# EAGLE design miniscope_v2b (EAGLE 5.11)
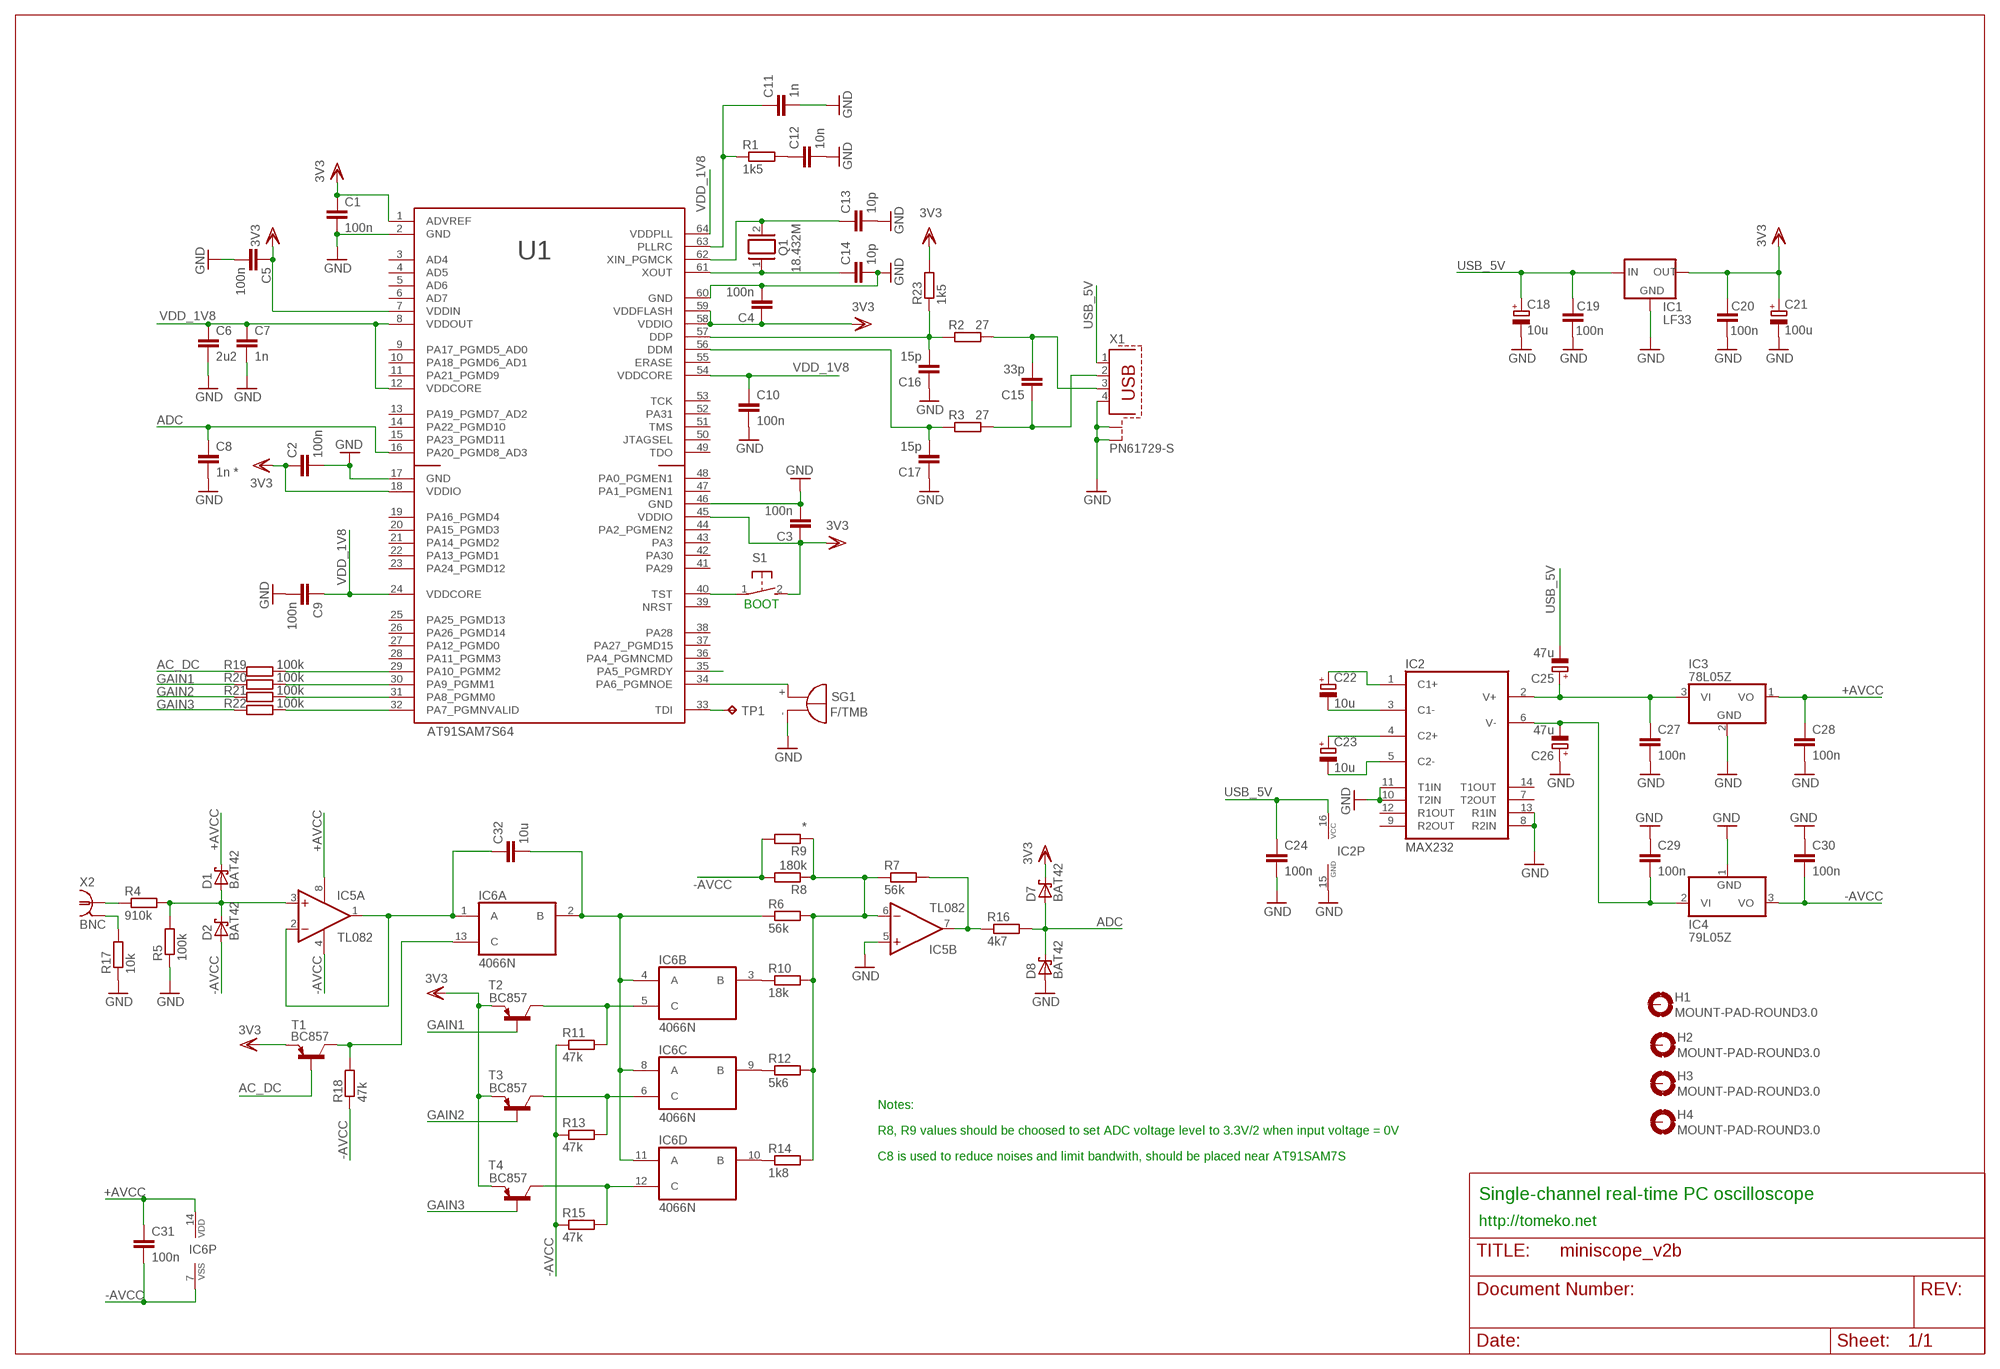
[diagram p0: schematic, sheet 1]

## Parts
C1  100n  C-EUC0805K  [C0805K]
C2  100n  C-EUC0805K  [C0805K]
C3  100n  C-EUC0805K  [C0805K]
C4  100n  C-EUC0805K  [C0805K]
C5  100n  C-EUC0805K  [C0805K]
C6  2u2  C-EUC1206K  [C1206K]
C7  1n  C-EUC0805K  [C0805K]
C8  1n *  C-EUC0805K  [C0805K]
C9  100n  C-EUC0805K  [C0805K]
C10  100n  C-EUC0805K  [C0805K]
C11  1n  C-EUC0805K  [C0805K]
C12  10n  C-EUC0805K  [C0805K]
C13  10p  C-EUC0805K  [C0805K]
C14  10p  C-EUC0805K  [C0805K]
C15  33p  C-EUC0805K  [C0805K]
C16  15p  C-EUC0805K  [C0805K]
C17  15p  C-EUC0805K  [C0805K]
C18  10u  CPOL-EUE2.5-5  [E2,5-5]
C19  100n  C-EUC0805K  [C0805K]
C20  100n  C-EUC0805K  [C0805K]
C21  100u  CPOL-EUE2.5-6  [E2,5-6]
C22  10u  CPOL-EUE2.5-5  [E2,5-5]
C23  10u  CPOL-EUE2.5-5  [E2,5-5]
C24  100n  C-EUC0805K  [C0805K]
C25  47u  CPOL-EUE2.5-6  [E2,5-6]
C26  47u  CPOL-EUE2.5-6  [E2,5-6]
C27  100n  C-EUC0805K  [C0805K]
C28  100n  C-EUC0805K  [C0805K]
C29  100n  C-EUC0805K  [C0805K]
C30  100n  C-EUC0805K  [C0805K]
C31  100n  C-EUC0805K  [C0805K]
C32  10u  C-EUC1206K  [C1206K]
D1  BAT42  [DO35-10]
D2  BAT42  [DO35-10]
D7  BAT42  [DO35-10]
D8  BAT42  [DO35-10]
H1  MOUNT-PAD-ROUND3.0  [3,0-PAD]
H2  MOUNT-PAD-ROUND3.0  [3,0-PAD]
H3  MOUNT-PAD-ROUND3.0  [3,0-PAD]
H4  MOUNT-PAD-ROUND3.0  [3,0-PAD]
IC1  LF33  LFXXCV  [DPACK_1]
IC2  MAX232  [DIL16]
IC3  78L05Z  [TO92]
IC4  79L05Z  [TO92]
IC5  TL082  NE5532N  [DIL08]
IC6  4066N  [DIL14]
Q1  18.432M  XTAL/S  [QS]
R1  1k5  R-R0805  [R0805]
R2  27  R-R0805  [R0805]
R3  27  R-R0805  [R0805]
R4  910k  R-R0805  [R0805]
R5  100k  R-R0805  [R0805]
R6  56k  R-R0805  [R0805]
R7  56k  R-R0805  [R0805]
R8  180k  R-R0805  [R0805]
R9  *  R-R0805  [R0805]
R10  18k  R-R0805  [R0805]
R11  47k  R-R0805  [R0805]
R12  5k6  R-R0805  [R0805]
R13  47k  R-R0805  [R0805]
R14  1k8  R-R0805  [R0805]
R15  47k  R-R0805  [R0805]
R16  4k7  R-R0805  [R0805]
R17  10k  R-R0805  [R0805]
R18  47k  R-R0805  [R0805]
R19  100k  R-R0805  [R0805]
R20  100k  R-R0805  [R0805]
R21  100k  R-R0805  [R0805]
R22  100k  R-R0805  [R0805]
R23  1k5  R-R0805  [R0805]
S1  31-XX  [B3F-31XX]
SG1  F/TMB  [F/TMB]
T1  BC857  BC857B-PNP-SOT23-BEC  [SOT23-BEC]
T2  BC857  BC857B-PNP-SOT23-BEC  [SOT23-BEC]
T3  BC857  BC857B-PNP-SOT23-BEC  [SOT23-BEC]
T4  BC857  BC857B-PNP-SOT23-BEC  [SOT23-BEC]
TP1  TPPAD1-13  [P1-13]
U1  AT91SAM7S64  AT91SAM7S64_LQFP64  [LQFP64]
X1  PN61729-S  [PN61729-S]
X2  BNC  1-227161-0  [AMP_227161]

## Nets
+AVCC: C28.1 C31.1 D1.C IC3.1(VO) IC5.8(P:V+) IC6.14(P:VDD)
-AVCC: C30.2 C31.2 D2.A IC4.3(VO) IC5.4(P:V-) IC6.7(P:VSS) R8.2 R9.2 R11.1 R13.1 R15.1 R18.1
AC_DC: R19.1 T1.B
ADC: C8.1 D7.A D8.C R16.2 U1.16(PA20_PGMD8_AD3)
GAIN1: R20.1 T2.B
GAIN2: R21.1 T3.B
GAIN3: R22.1 T4.B
GND: C1.2 C2.2 C3.2 C4.2 C5.2 C6.2 C7.2 C8.2 C9.2 C10.2 C11.2 C12.2 C13.2 C14.2 C16.1 C17.1 C18.- C19.1 C20.1 C21.- C24.2 C26.+ C27.2 C28.2 C29.1 C30.1 D8.A IC1.C(GND) IC2.8(R2IN) IC2.10(T2IN) IC2.11(T1IN) IC2.13(R1IN) IC2.15(GND) IC3.2(GND) IC4.1(GND) IC5.5(B:+IN) R5.1 R17.1 SG1.- U1.2(GND) U1.17(GND) U1.46(GND) U1.60(GND) X1.4 X1.S1 X1.S2
N$1: S1.1(P) U1.40(TST)
N$2: C11.1 R1.1 U1.63(PLLRC)
N$3: C12.1 R1.2
N$4: C14.1 Q1.1 U1.61(XOUT)
N$5: C13.1 Q1.2 U1.62(XIN_PGMCK)
N$6: C16.2 R2.1 R23.1 U1.57(DDP)
N$7: C17.2 R3.1 U1.56(DDM)
N$8: C15.2 R2.2 X1.3
N$9: C15.1 R3.2 X1.2
N$10: C25.+ C27.1 IC2.2(V+) IC3.3(VI)
N$11: C22.- IC2.3(C1-)
N$12: C22.+ IC2.1(C1+)
N$13: C23.+ IC2.4(C2+)
N$14: C23.- IC2.5(C2-)
N$15: R4.1 X2.1
N$16: C26.- C29.2 IC2.6(V-) IC4.2(VI)
N$17: D1.A D2.C IC5.3(A:+IN) R4.2 R5.2
N$18: C32.1 IC5.1(A:OUT) IC5.2(A:-IN) IC6.1(A:A)
N$19: R17.2 X2.2(GND)
N$20: C32.2 IC6.2(A:B) IC6.4(B:A) IC6.8(C:A) IC6.11(D:A) R6.1
N$21: IC5.6(B:-IN) R6.2 R7.1 R8.1 R9.1 R10.2 R12.2 R14.2
N$22: IC5.7(B:OUT) R7.2 R16.1
N$23: IC6.9(C:B) R12.1
N$24: IC6.6(C:C) R13.2 T3.C
N$25: IC6.3(B:B) R10.1
N$26: IC6.10(D:B) R14.1
N$27: IC6.5(B:C) R11.2 T2.C
N$28: R19.2 U1.29(PA10_PGMM2)
N$29: IC6.12(D:C) R15.2 T4.C
N$30: R20.2 U1.30(PA9_PGMM1)
N$31: IC6.13(A:C) R18.2 T1.C
N$32: R21.2 U1.31(PA8_PGMM0)
N$33: R22.2 U1.32(PA7_PGMNVALID)
N$34: SG1.+ U1.34(PA6_PGMNOE)
N$35: U1.35(PA5_PGMRDY)
N$36: TP1.TP U1.33(TDI)
USB_5V: C18.+ C19.2 C24.1 C25.- IC1.B(IN) IC2.16(VCC) X1.1
VDD: C1.1 C2.1 C3.1 C4.1 C5.1 C20.2 C21.+ D7.C IC1.E(OUT) R23.2 S1.2(S) T1.E T2.E T3.E T4.E U1.1(ADVREF) U1.7(VDDIN) U1.18(VDDIO) U1.45(VDDIO) U1.58(VDDIO) U1.59(VDDFLASH) ; supply symbol labelled 3V3
VDD_1V8: C6.1 C7.1 C9.1 C10.1 U1.8(VDDOUT) U1.12(VDDCORE) U1.24(VDDCORE) U1.54(VDDCORE) U1.64(VDDPLL)
Unconnected: H1.B3,0(MOUNT) H2.B3,0(MOUNT) H3.B3,0(MOUNT) H4.B3,0(MOUNT) IC2.7(T2OUT) IC2.9(R2OUT) IC2.12(R1OUT) IC2.14(T1OUT) U1.3(AD4) U1.4(AD5) U1.5(AD6) U1.6(AD7) U1.9(PA17_PGMD5_AD0) U1.10(PA18_PGMD6_AD1) U1.11(PA21_PGMD9) U1.13(PA19_PGMD7_AD2) U1.14(PA22_PGMD10) U1.15(PA23_PGMD11) U1.19(PA16_PGMD4) U1.20(PA15_PGMD3) U1.23(PA24_PGMD12) U1.25(PA25_PGMD13) U1.26(PA26_PGMD14) U1.27(PA12_PGMD0) U1.28(PA11_PGMM3) U1.36(PA4_PGMNCMD) U1.37(PA27_PGMD15) U1.38(PA28) U1.39(NRST) U1.41(PA29) U1.42(PA30) U1.43(PA3) U1.44(PA2_PGMEN2) U1.47(PA1_PGMEN1) U1.48(PA0_PGMEN1) U1.49(TDO) U1.50(JTAGSEL) U1.51(TMS) U1.55(ERASE)

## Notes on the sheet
- BOOT
- Notes:
- R8, R9 values should be choosed to set ADC voltage level to 3.3V/2 when input voltage = 0V
- C8 is used to reduce noises and limit bandwith, should be placed near AT91SAM7S
- Single-channel real-time PC oscilloscope
- http://tomeko.net

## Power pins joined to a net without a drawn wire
PA13_PGMD1: U1.22(PA13_PGMD1)
PA14_PGMD2: U1.21(PA14_PGMD2)
PA31: U1.52(PA31)
TCK: U1.53(TCK)

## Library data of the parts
C1-C17 C19 C20 C24 C27-C32 = resistor:C-EU: CAPACITOR, European symbol
C18 C21-C23 C25 C26 = resistor:CPOL-EU: POLARIZED CAPACITOR, European symbol
D1 D2 D7 D8 = diode:BAT42: DIODE
H1-H4 = holes:MOUNT-PAD-ROUND: MOUNTING PAD, round
IC1 = lf33:LFXXCV: VOLTAGE REGULATOR
IC2 = maxim:MAX232: RS232 TRANSEIVER; MF: MAXIM; MPN: MAX232ACPE+; OC_FARNELL: 9723773; OC_NEWARK: 68K4544
IC3 = linear:78*: Positive VOLTAGE REGULATOR Source: http://cache.national.com/ds/LM/LM78L05.pdf http://www.fairchildsemi.com/ds/LM/LM7805.pdf
IC4 = linear:79*: Negative VOLTAGE REGULATOR
IC5 = linear:NE5532: AUDIO AMPLIFIER
IC6 = 40xx:4066: Quad bilateral ANALOG SWITCH
Q1 = special:XTAL/S: CRYSTAL
R1-R23 = quantum-sensor:R: Resistor
S1 = switch-omron:31-XX: OMRON SWITCH; MPN: B3F-3100; OC_FARNELL: 959704; OC_NEWARK: 36M3582
SG1 = buzzer:F/TMB: BUZZER; OC_FARNELL: unknown; OC_NEWARK: unknown
T1-T4 = transistor:*-PNP-: PNP Transistror
TP1 = testpad:TP: Test pad
U1 = atmel_prototype_header:AT91SAM7S64: Atmel AT91 ARM Thumb-based Microcontroller. LQFP64 package.
X1 = con-berg:PN61729-S: BERG USB connector; OC_FARNELL: unknown; OC_NEWARK: unknown
X2 = con-coax:?227161*: JACK, RIGHT ANGLE, 50 OHM, PCB, BNC; MF: TYCO ELECTRONICS; MPN: 1-227161; OC_FARNELL: unknown; OC_NEWARK: 33B3200

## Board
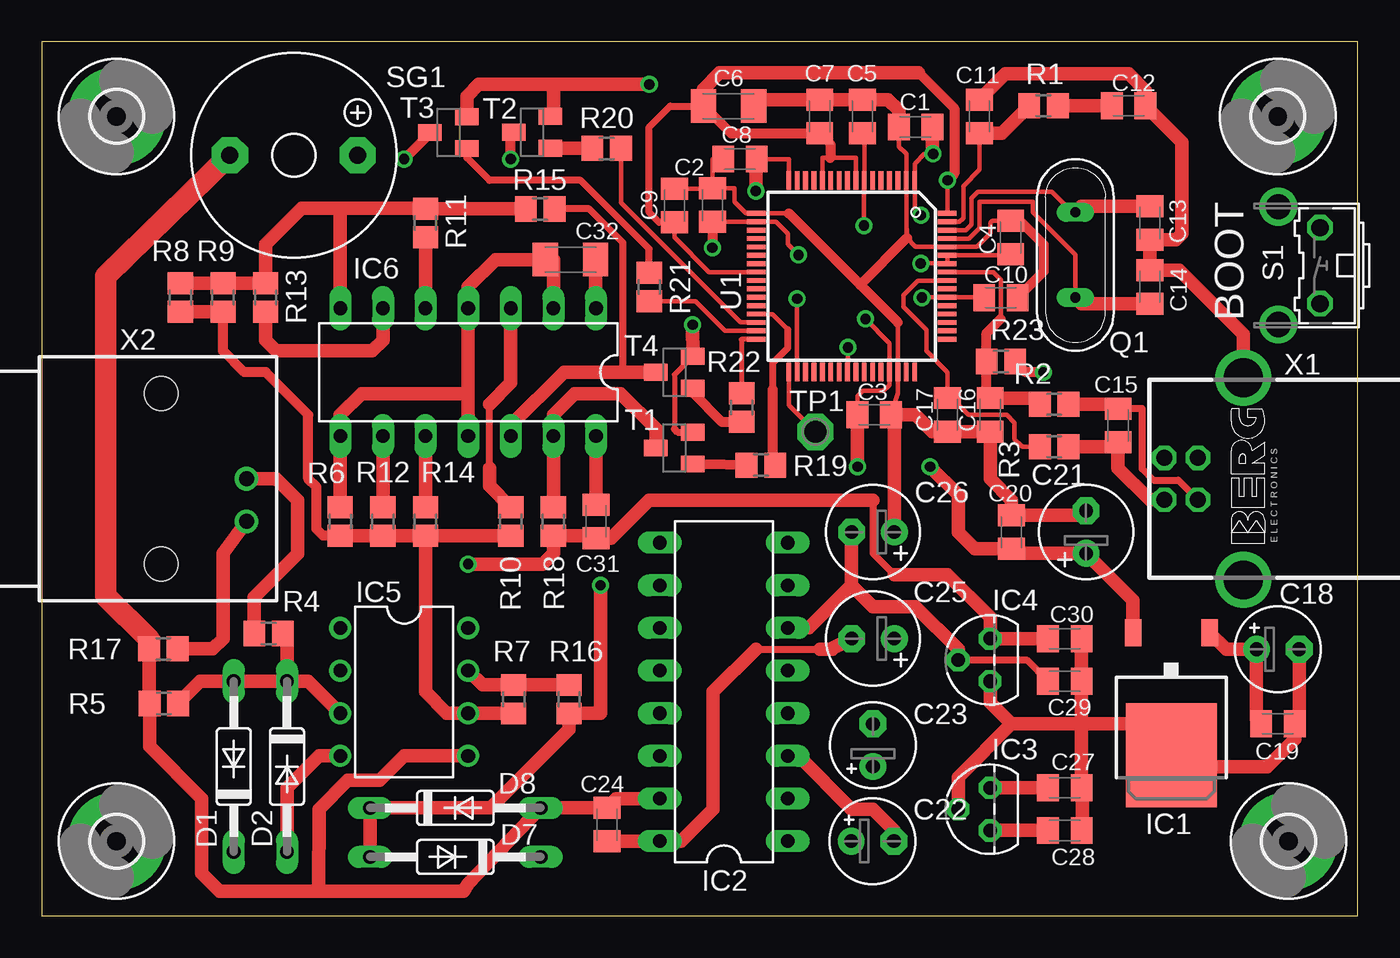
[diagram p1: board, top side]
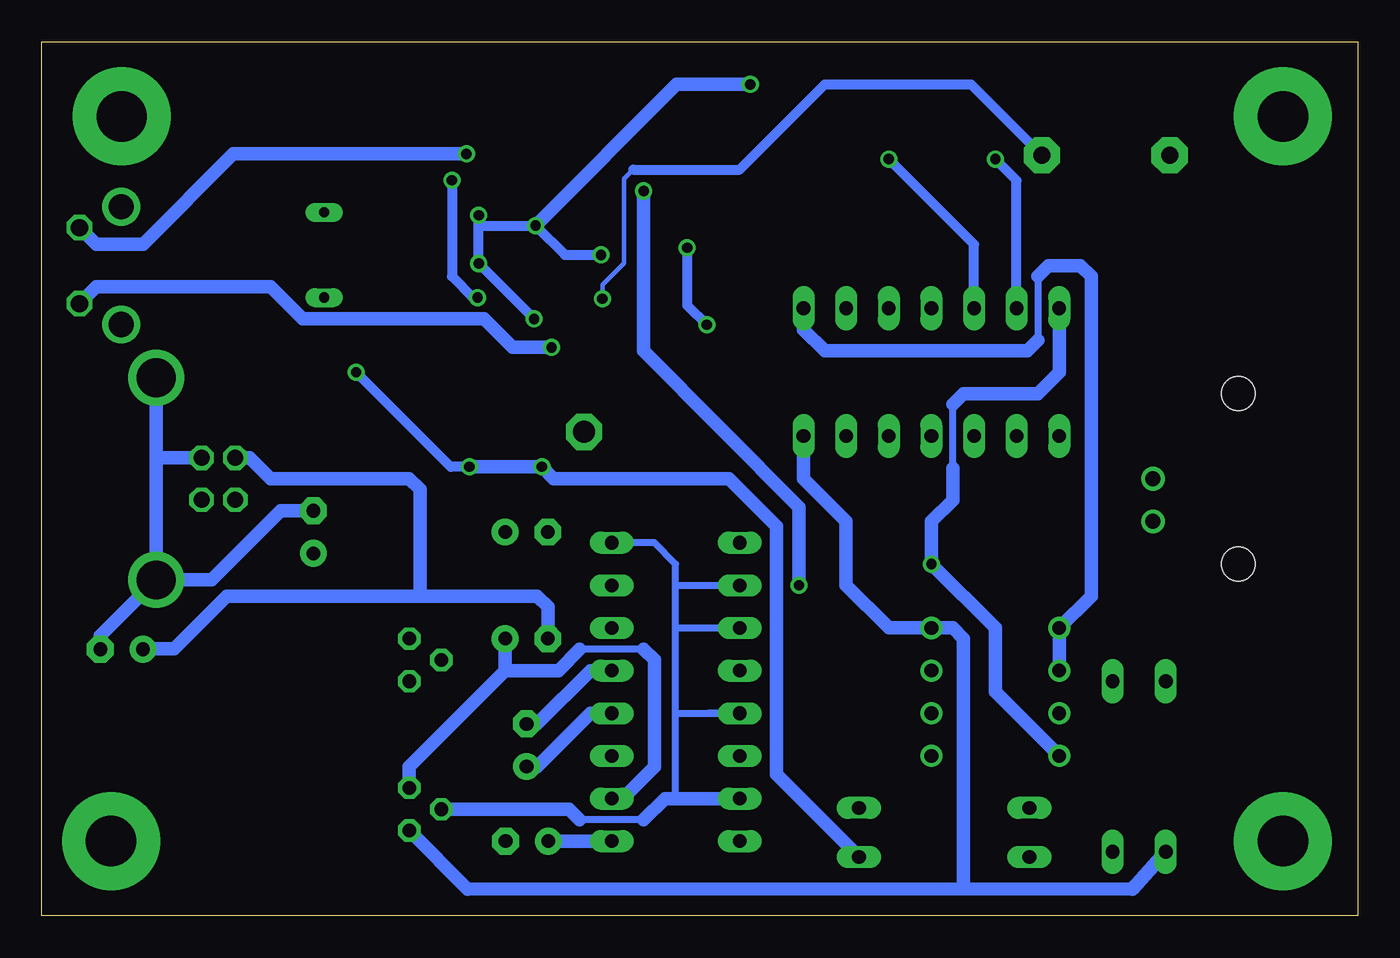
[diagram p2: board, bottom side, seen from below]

Size 78.41 x 52.06 mm. Coordinates in mm from the lower left corner, seen from the top.
Outline: 0,0 78.41,0 78.41,52.06 0,52.06 0,0
Copper layers (1*16): Top 0.035mm / dielectric 1.5mm / Bottom 0.035mm
Design rules "default *": minimum track width 10mil, minimum drill 24mil, track to track 8mil, track to pad 8mil, pad to pad 8mil, via to via 8mil, smd to smd 8mil, copper to edge 40mil, drill to drill 8mil, minimum pad ring 10mil, minimum via ring 8mil, stop-mask expansion 4mil, vias tented up to drill 0mil, thermal gap 10mil

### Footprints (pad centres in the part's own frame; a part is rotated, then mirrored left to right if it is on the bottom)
C0805K = smd 1.3 x 1.6: 1 -1,0; 2 1,0
C1206K = smd 1.5 x 2: 1 -1.5,0; 2 1.5,0
E2,5-5 = drill 0.813 pad 1.6 round: + -1.27,0 | drill 0.813 pad 1.6 octagon: - 1.27,0
E2,5-6 = drill 0.813 pad 1.6 round: + -1.27,0 | drill 0.813 pad 1.6 octagon: - 1.27,0
DO35-10 = drill 0.813 long: A 5.08,0; C -5.08,0
3,0-PAD = drill 3 pad 5.842 round: B3,0 0,0
DPACK_1 = smd 1 x 1.6: B -2.28,-4.8; E 2.28,-4.8 | smd 5.4 x 6.2: C 0,2.5
DIL16 = drill 0.813 long: 1 -8.89,-3.81; 2 -6.35,-3.81; 3 -3.81,-3.81; 4 -1.27,-3.81; 5 1.27,-3.81; 6 3.81,-3.81; 7 6.35,-3.81; 8 8.89,-3.81; 9 8.89,3.81; 10 6.35,3.81; 11 3.81,3.81; 12 1.27,3.81; 13 -1.27,3.81; 14 -3.81,3.81; 15 -6.35,3.81; 16 -8.89,3.81
TO92 = drill 0.813 octagon: 1 -1.27,0; 2 0,1.905; 3 1.27,0
DIL08 = drill 0.813 pad 1.27 round: 1 -3.81,-3.81; 2 -1.27,-3.81; 3 1.27,-3.81; 4 3.81,-3.81; 5 3.81,3.81; 6 1.27,3.81; 7 -1.27,3.81; 8 -3.81,3.81
DIL14 = drill 0.813 long: 1 -7.62,-3.81; 2 -5.08,-3.81; 3 -2.54,-3.81; 4 0,-3.81; 5 2.54,-3.81; 6 5.08,-3.81; 7 7.62,-3.81; 8 7.62,3.81; 9 5.08,3.81; 10 2.54,3.81; 11 0,3.81; 12 -2.54,3.81; 13 -5.08,3.81; 14 -7.62,3.81
QS = drill 0.61 long: 1 -2.54,0; 2 2.54,0
R0805 = smd 1.3 x 1.5: 1 -0.85,0; 2 0.85,0
B3F-31XX = drill 1.016 octagon: 1 -2.261,-1.245; 2 2.261,-1.245 | drill 1.499 pad 2.159 round: 3 -3.505,1.245; 4 3.505,1.245
F/TMB = drill 1.016 pad 2.159 octagon: + 3.81,0; - -3.81,0
SOT23-BEC = smd 1 x 1.4: B -0.95,-1.1; C 0,1.1; E 0.95,-1.1
P1-13 = drill 1.321 pad 2.159 octagon: TP 0,0
LQFP64 = smd 1.1 x 0.285: 1 -5.7,3.75; 2 -5.7,3.25; 3 -5.7,2.75; 4 -5.7,2.25; 5 -5.7,1.75; 6 -5.7,1.25; 7 -5.7,0.75; 8 -5.7,0.25; 9 -5.7,-0.25; 10 -5.7,-0.75; 11 -5.7,-1.25; 12 -5.7,-1.75; 13 -5.7,-2.25; 14 -5.7,-2.75; 15 -5.7,-3.25; 16 -5.7,-3.75; 33 5.7,-3.75; 34 5.7,-3.25; 35 5.7,-2.75; 36 5.7,-2.25; 37 5.7,-1.75; 38 5.7,-1.25; 39 5.7,-0.75; 40 5.7,-0.25; 41 5.7,0.25; 42 5.7,0.75; 43 5.7,1.25; 44 5.7,1.75; 45 5.7,2.25; 46 5.7,2.75; 47 5.7,3.25; 48 5.7,3.75 | smd 0.285 x 1.1: 17 -3.75,-5.7; 18 -3.25,-5.7; 19 -2.75,-5.7; 20 -2.25,-5.7; 21 -1.75,-5.7; 22 -1.25,-5.7; 23 -0.75,-5.7; 24 -0.25,-5.7; 25 0.25,-5.7; 26 0.75,-5.7; 27 1.25,-5.7; 28 1.75,-5.7; 29 2.25,-5.7; 30 2.75,-5.7; 31 3.25,-5.7; 32 3.75,-5.7; 49 3.75,5.7; 50 3.25,5.7; 51 2.75,5.7; 52 2.25,5.7; 53 1.75,5.7; 54 1.25,5.7; 55 0.75,5.7; 56 0.25,5.7; 57 -0.25,5.7; 58 -0.75,5.7; 59 -1.25,5.7; 60 -1.75,5.7; 61 -2.25,5.7; 62 -2.75,5.7; 63 -3.25,5.7; 64 -3.75,5.7
PN61729-S = drill 0.95 octagon: 1 1.25,4.71; 2 -1.25,4.71; 3 -1.25,2.71; 4 1.25,2.71 | drill 2.3 pad 2.9 round: S1 -6.02,0; S2 6.02,0
AMP_227161 = drill 0.9 pad 1.27 round: 1 0,-5.08; 2 -2.54,-5.08 | hole 2: -5.08,0; 5.08,0

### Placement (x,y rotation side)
C1  52.07,46.99 180 top
C2  39.95,42.34 90 top
C3  49.61,29.84 0 top
C4  57.73,40.41 90 top
C5  48.9,47.62 90 top
C6  40.92,48.23 0 top
C7  46.35,47.62 90 top
C8  41.61,45.09 180 top
C9  37.69,42.32 90 top
C10  57.15,36.83 0 top
C11  55.88,47.62 90 top
C12  64.77,48.26 0 top
C13  66.04,41.27 270 top
C14  66.04,37.47 90 top
C15  64.14,29.21 90 top
C16  56.52,29.84 90 top
C17  53.98,29.84 90 top
C18  73.66,15.88 0 top
C19  73.66,11.43 180 top
C20  57.78,22.86 270 top
C21  62.23,22.86 90 top
C22  49.5,4.45 0 top
C23  49.53,10.16 90 top
C24  33.68,5.44 90 top
C25  49.53,16.51 180 top
C26  49.53,22.86 180 top
C27  60.96,7.62 0 top
C28  60.96,5.08 0 top
C29  60.96,13.97 180 top
C30  60.96,16.51 180 top
C31  33.02,23.5 270 top
C32  31.5,39.09 180 top
D1  11.43,8.89 90 top
D2  14.61,8.89 270 top
D7  24.64,3.51 180 top
D8  24.64,6.43 0 top
H1  74.3,4.45 0 top
H2  73.66,47.62 0 top
H3  4.45,47.62 0 top
H4  4.45,4.45 0 top
IC1  67.31,12.06 180 top
IC2  40.64,13.34 90 top
IC3  56.52,6.35 90 top
IC4  56.52,15.24 90 top
IC5  21.59,13.34 270 top
IC6  25.4,32.38 180 top
Q1  61.59,39.37 90 top
R1  59.69,48.26 0 top
R2  60.33,30.48 0 top
R3  60.33,27.94 0 top
R4  13.51,16.81 0 top
R5  7.26,12.65 0 top
R6  17.78,23.5 270 top
R7  28.12,12.9 90 top
R8  8.26,36.83 90 top
R9  10.79,36.83 90 top
R10  27.94,23.5 270 top
R11  22.86,41.27 270 top
R12  20.32,23.5 270 top
R13  13.34,36.83 270 top
R14  22.86,23.5 270 top
R15  29.69,42.11 0 top
R16  31.42,12.9 270 top
R17  7.24,15.9 0 top
R18  30.48,23.5 90 top
R19  42.85,26.85 0 top
R20  33.66,45.72 0 top
R21  36.2,37.47 270 top
R22  41.71,30.28 90 top
R23  57.15,33.02 0 top
S1  74.93,38.73 90 top
SG1  15.01,45.31 0 top
T1  37.69,27.86 90 top
T2  29.21,46.69 90 top
T3  24.23,46.66 90 top
T4  37.69,32.38 90 top
TP1  46.1,28.83 0 top
U1  48.26,38.1 270 top
X1  71.6,26.04 90 top
X2  7.11,26.04 90 top

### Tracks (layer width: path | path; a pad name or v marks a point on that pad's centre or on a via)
+AVCC
  Top 0.813: IC3.1 C28.1 | IC6.14 C31.1
  Bottom 0.813: D1.C 13.44,1.57 23.29,1.6 23.5,1.6 | 23.5,1.6 53.03,1.57 IC3.1 | IC6.14 33.02,26.04 30.48,23.5 30.48,19.68 27.94,17.14 IC5.8 24.13,17.14 23.5,16.51 23.5,1.6 | 23.5,1.6
-AVCC  (via drill 0.61)
  Top 0.254: R11.1 22.81,42.14
  Top 0.406: 49.53,24.77 49.53,21.59 50.8,20.32
  Top 0.813: R8.2 R9.2 R13.1 13.34,40.01 15.47,42.14 17.78,42.14 | C30.2 IC4.3 56.52,17.78 53.98,20.32 50.8,20.32 | 49.53,24.77 36.2,24.77 33.92,22.5 C31.2 32.87,22.64 R18.1 30.48,21.59 29.84,20.95 v25.4,20.95 | D2.A 14.61,7.62 16.51,9.53 IC5.4 | R15.1 27.51,42.12 R11.1 22.85,42.14 17.78,42.14 | IC6.7 17.78,42.14
  Bottom 0.406: 24.13,26.67 24.13,30.48
  Bottom 0.813: IC5.4 21.59,13.34 21.59,17.14 v25.4,20.95 25.4,23.5 24.13,24.77 24.13,26.67 | 24.13,30.48 23.5,31.11 19.05,31.11 17.78,32.38 IC6.7
AC_DC
  Top 0.61: R19.1 39.44,26.9 T1.B
ADC  (via drill 0.61)
  Top 0.254: U1.16 44.51,45.09 C8.1
  Top 0.813: D7.A D8.C 26.75,6.43 31.42,11.1 R16.2 33.3,12.05 v33.3,19.68 | v42.55,43.18 42.55,45.02 C8.1
  Bottom 0.813: v33.3,19.68 33.3,24.33 42.55,33.66 v42.55,43.18
GAIN1
  Top 0.813: T2.B 32.79,45.73 R20.1
GAIN2
  Top 0.406: R21.1 36.2,39.73 32.11,43.81 26.67,43.81 25.33,45.15 T3.B
GAIN3
  Top 0.61: R22.1 41.69,29.41 40.54,29.41 38.79,31.16 T4.B
GND
  Top 0.254: 51.51,41.53 U1.2 51.51,45.39 51.08,45.82 C1.2 | 51.56,40.39 51.51,41.53 | 44.51,41.85 U1.17 41.97,41.85 41.27,42.55 41.27,43.34 C2.2 | 51.01,35.35 U1.46 51,31.14 C3.2 | 51.51,41.53 51.51,40.44 51.56,40.39 | 51.56,40.39 52.07,39.85 53.93,39.85 U1.60 55.73,39.85 56.52,40.66 56.52,41.27 56.65,41.41 C4.2 | 62,5.08 C28.2 | C27.2 62,7.62 | R5.1 6.4,12.7 | 6.4,15.85 R17.1 | 74.37,9.96 74.68,10.26 74.68,11.38 C19.1 | 67.36,9.96 67.36,9.65 IC1.C | C2.2 39.95,45.09 C8.2 | C2.2 39.95,43.32 C9.2
  Top 0.406: C7.2 45.97,48.23
  Top 0.61: 48.77,37.59 51.56,40.39 | 48.77,37.59 44.51,41.85 | 51.01,35.35 48.77,37.59 | C10.2 59.69,38.37 59.69,40.01 58.28,41.41 C4.2
  Top 0.813: 6.4,15.85 6.4,12.66 R5.1 6.41,10.1 9.53,6.99 9.53,2.54 10.59,1.45 16.48,1.45 | IC2.15 34.23,6.99 C24.2 D8.A 25.4,1.91 25.12,1.47 16.48,1.45 | IC5.5 21.59,9.53 20.12,8.08 18.21,8.08 16.51,6.35 16.48,1.45 | 62,5.08 62,7.58 C27.2 61.96,11.43 | C30.1 C29.1 61.96,11.43 | IC4.1 56.52,12.7 57.78,11.43 | 57.78,11.43 61.96,11.43 | 61.96,11.43 65.44,11.43 IC1.C | IC3.2 54.61,8.26 57.78,11.43 | C18.- 74.93,11.7 C19.1 74.66,10.53 73.03,8.89 68.43,8.89 67.36,9.96 | C21.- 61.96,23.86 C20.1 57.78,24.77 56.52,26.04 C16.1 C17.1 53.07,28.84 52.07,29.84 C3.2 50.8,29.65 C26.+ | X1.S2 71.6,34.65 67.78,38.47 C14.2 C13.2 67.58,40.27 67.94,40.64 67.94,46.09 C12.2 65.77,49.16 64.77,50.16 57.42,50.16 C11.2 | C1.2 51.07,47.99 50.44,48.62 C5.2 C7.2 42.81,48.62 C6.2
  Top 1.27: SG1.- 3.81,38.1 3.81,19.05 6.39,16.47 R17.1
  Bottom 0.406: 42.55,5.71 46.35,5.71 | IC2.8 41.91,22.23 40.64,20.95 40.64,19.68 | 38.73,12.06 IC2.13 40.64,12.06 | 40.64,6.99 40.64,12.06 | 40.64,12.06 40.64,17.14 | 40.64,17.14 40.64,19.68 | 40.64,19.68 IC2.10 | 40.64,17.14 IC2.11
  Bottom 0.813: X1.S1 74.93,16.69 C18.- | IC2.15 40.64,6.99 41.27,6.99 42.55,5.71 | 46.35,5.71 46.99,6.35 IC3.2 | C21.- 64.19,24.13 68.3,20.02 X1.S1 | X1.S1 71.6,27.3 | 71.6,27.3 X1.S2 | X1.4 71.58,27.29 71.6,27.3
N$1  (via drill 0.61)
  Top 0.254: U1.40 48.03,32.42 v48.03,33.86
  Bottom 0.254: v48.03,33.86 48.11,33.93
  Bottom 0.813: S1.1 75.18,37.47 64.77,37.47 62.87,35.56 52.07,35.56 50.37,33.86 v48.03,33.86
N$2
  Top 0.254: U1.63 54.69,41.35 54.91,41.55 54.91,43.46 55.88,44.45 C11.1
  Top 0.813: C11.1 57.2,46.62 R1.1
N$3
  Top 0.813: R1.2 C12.1
N$4
  Top 0.254: Q1.1 61.59,39.37 59.05,41.91 59.05,42.55 55.88,42.55 55.88,41.02 55.91,41 55.26,40.35 U1.61
  Top 0.813: C14.1 61.96,36.47 Q1.1
N$5
  Top 0.254: U1.62 55.07,40.84 55.4,41.17 55.4,42.75 55.78,43.13 60.2,43.13 61.42,41.91 Q1.2
  Top 0.813: C13.1 61.96,42.27 Q1.2
N$6
  Top 0.254: U1.57 56.69,38.35 57.15,37.9 57.15,35.56
  Top 0.61: C16.2 56.3,31.06 R23.1 56.3,34.71 57.15,35.56
  Top 0.813: C16.2 59.11,30.84 R2.1
N$7
  Top 0.254: U1.56 52.22,37.85 51.36,36.98 51.36,36.27 52.7,34.92 52.7,33.66 53.98,32.38 C17.2 54.22,30.84 55.22,29.84 57.51,29.84 57.96,29.39 57.96,28.4 58.42,27.94 R3.1
N$8
  Top 0.406: X1.3 67.72,25.96 66.24,25.96 65.58,26.62 65.58,30.21 C15.2
  Top 0.813: R2.2 63.87,30.48 C15.2
N$9
  Top 0.813: X1.2 66.02,24.79 64.14,26.67 C15.1 63.87,27.94 R3.2
N$10
  Top 0.813: IC3.3 C27.1
  Bottom 0.406: 42.55,15.88 46.35,15.88
  Bottom 0.813: IC3.3 56.52,8.89 50.8,14.61 | 50.8,14.61 C25.+ | IC2.2 43.81,6.99 41.91,8.89 41.91,15.24 42.55,15.88 | 46.35,15.88 47.62,14.61 50.8,14.61
N$11
  Top 0.813: C22.- 50.77,5.11 49.53,6.35 48.26,6.35 45.09,9.53 IC2.3
N$12
  Bottom 0.813: IC2.1 C22.+
N$13
  Bottom 0.813: C23.+ 48.9,8.89 45.72,12.06 IC2.4
N$14
  Bottom 0.813: C23.- 48.9,11.43 45.72,14.61 IC2.5
N$15
  Top 0.813: X2.1 13.97,26.04 15.24,24.77 15.24,21.57 12.65,18.97 12.65,16.83 R4.1
N$16
  Top 0.406: IC4.2 58.69,15.24 C29.2
  Top 0.813: IC2.6 45.72,17.14 48.26,19.68 | 48.26,19.68 C26.- | IC4.2 54.61,15.88 52.07,18.41 49.53,18.41 48.26,19.68
N$17
  Top 0.813: R5.2 9.44,13.97 D1.A D2.C | R4.2 arc-90 14.61,16.57 D2.C | IC5.3 15.88,13.97 D2.C
N$18
  Top 0.813: IC6.1 33,36.22 C32.1
  Bottom 0.406: 19.05,38.1 19.05,34.29
  Bottom 0.813: IC5.2 IC5.1 15.88,19.05 15.88,38.1 16.51,38.73 18.41,38.73 19.05,38.1 | 19.05,34.29 19.68,33.66 31.75,33.66 33.02,34.92 IC6.1
N$19
  Top 0.813: R17.2 10.19,15.9 10.79,16.51 10.79,21.59 X2.2
N$20
  Top 0.813: R6.1 IC6.8 17.78,29.84 19.05,31.11 25.4,31.11 | 25.4,31.11 IC6.11 | 25.4,31.11 IC6.4 25.4,37.47 27.03,39.09 C32.2 30.48,39.09 IC6.2
N$21
  Top 0.61: R6.2 16.75,22.64 16.36,23.04 16.36,25.55 15.88,26.04 15.88,29.84 13.34,32.38 12.06,32.38 10.79,33.66 R9.1
  Top 0.813: R6.2 R12.2 R14.2 | R14.2 R10.2 | R14.2 22.86,13.34 24.13,12.06 IC5.6 25.41,12.05 R7.1 | R8.1 R9.1
N$22
  Top 0.813: IC5.7 26.25,13.75 R7.2 R16.1
N$23
  Top 0.813: R12.1 IC6.9
N$24  (via drill 0.61)
  Top 0.61: v21.59,45.09 23.13,46.63 T3.C
  Top 0.813: IC6.6 20.32,34.29 19.68,33.66 13.97,33.66 13.34,34.29 R13.2
  Bottom 0.61: IC6.6 20.32,43.81 v21.59,45.09
N$25
  Top 0.406: 26.67,26.67 26.67,30.48
  Top 0.813: R10.1 26.67,25.61 26.67,26.67 | 26.67,30.48 27.94,31.75 IC6.3
N$26
  Top 0.813: R14.1 IC6.10
N$27  (via drill 0.61)
  Top 0.61: T2.C 27.94,46.52 v27.94,45.09
  Top 0.813: IC6.5 R11.2
  Bottom 0.61: v27.94,45.09 22.86,40.01 IC6.5
N$28
  Top 0.254: 44.45,34.92 43.52,35.85 U1.29
  Top 0.406: 43.56,31.37 43.56,32.94 44.45,33.83 44.45,34.92
  Top 0.61: 43.56,31.37 43.56,26.99 R19.2
N$29
  Top 0.406: 34.92,32.38 34.62,32.69 34.62,40.11 32.61,42.11 R15.2
  Top 0.813: IC6.12 27.94,29.21 31.11,32.38 34.92,32.38 T4.C
N$30
  Top 0.254: U1.30 41.64,35.35 34.51,42.48 R20.2
N$31
  Top 0.813: R18.2 IC6.13 30.48,29.84 31.75,31.11 34.49,31.11 36.59,29.02 T1.C
N$32
  Top 0.254: U1.31 40.72,34.85 38.95,36.62 R21.2
N$33
  Top 0.305: U1.32 41.68,34.34 41.71,34.31 R22.2
N$34  (via drill 0.61)
  Top 0.254: U1.34 v45.01,36.75
  Bottom 0.254: v45.01,36.75 45.01,37.59 43.71,38.89 43.71,43.92 43.18,44.45
  Bottom 0.61: 43.18,44.45 36.83,44.45 31.75,49.53 23.04,49.53 SG1.+
N$36
  Top 0.254: U1.33 44.51,30.42 TP1.TP
USB_5V
  Top 0.406: 42.55,15.88 46.35,15.88
  Top 0.813: C24.1 36.82,4.44 IC2.16 38.1,4.45 40.01,6.35 40.01,13.34 42.55,15.88 | C19.2 72.39,11.7 C18.+ 70.58,15.88 IC1.B | 47.24,16 46.99,15.88 | 47.24,16 C25.- | 46.35,15.88 47.12,15.88 47.24,16
  Bottom 0.813: C25.- 48.26,18.41 48.9,19.05 55.88,19.05 | 55.88,19.05 67.41,19.05 70.53,15.92 72.34,15.92 C18.+ | X1.1 66.02,27.29 64.77,26.04 56.52,26.04 55.88,25.4 55.88,19.05
VDD  (via drill 0.61)
  Top 0.254: U1.1 52.02,44.81 52.6,45.39 v53.11,45.39 | U1.1 | C2.1 39.33,41.35 U1.18 43.74,41.35 44.45,40.64 44.45,40.01 v45.09,39.37 | C4.1 57.04,39.35 U1.59 U1.58 53.95,38.86 v52.38,38.86 | C5.1 49.01,46.51 U1.7 49,43.79 v49,41.12 | U1.1 52.02,42.09 v52.38,41.73 | v49.07,35.56 50.51,34.12 U1.45 50.51,31.61 50.16,31.27 48.92,31.27 48.59,30.94 48.59,29.86 C3.1 48.9,29.84
  Top 0.305: 37.69,29.01 37.69,32.23 T4.E
  Top 0.406: T1.E 37.89,28.81 37.69,29.01
  Top 0.61: C2.1 v39.95,39.8 | R23.2 58.63,32.38 v59.69,32.38
  Top 0.813: IC1.E 65.03,18.79 C21.+ 58.05,21.59 C20.2 55.61,21.86 54.61,22.86 54.61,25.07 v52.93,26.75 | v53.11,45.39 53.07,45.43 C1.1 | v48.62,26.75 C3.1 | T3.E 25.33,48.83 26.04,49.53 30.48,49.53 | v38.79,35.2 T4.E | v36.2,49.53 30.48,49.53 | T2.E 30.48,47.63 30.48,49.53
  Bottom 0.254: v52.38,41.73 52.4,41.83
  Bottom 0.61: 52.38,41.12 v52.38,38.86 v49.07,35.56 | 52.38,41.12 v52.38,41.73 | v45.09,39.37 47.24,39.37 v49,41.12 52.38,41.12 | v38.79,35.2 39.95,36.37 v39.95,39.8 | v59.69,32.38 54.05,26.75 v52.93,26.75
  Bottom 0.813: S1.2 75.18,40.01 72.39,40.01 67,45.39 v53.11,45.39 | D7.C 34.65,8.43 34.65,23.22 37.47,26.04 47.9,26.04 v48.62,26.75 v52.93,26.75 | v36.2,49.53 40.59,49.53 v49,41.12
VDD_1V8  (via drill 0.61)
  Top 0.254: U1.8 48.51,44.73 48.51,45.16 46.99,45.16 46.51,45.16 46.51,44.5 U1.12 | 46.99,45.99 C7.1 46.22,46.76 | C10.1 56.13,36.85 U1.54 52.47,36.85 v52.45,36.83 | U1.64 53.96,43.8 v53.98,43.81 | U1.24 39.76,38.35 37.69,40.41 C9.1
  Top 0.406: C9.1 36.79,41.32 36.2,41.91 36.2,46.99 37.44,48.23 C6.1
  Top 0.61: 46.99,45.99 46.99,45.16 | 46.22,46.76 46.07,46.61 41.07,46.61 39.45,48.23 C6.1 | v53.98,43.81 54.38,44.22 54.38,48.11 52.27,50.22 52.25,50.22
  Top 0.813: 52.25,50.22 40.39,50.22 39.42,49.25 C6.1
  Bottom 0.61: v52.45,36.83 52.7,36.83 53.98,38.1 v53.98,43.81

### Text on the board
tNames: BOOT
